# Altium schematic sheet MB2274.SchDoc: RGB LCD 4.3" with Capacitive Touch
size A3; Date: 25-FEB-2015; Author: A.B; CompanyName: STMicroelectronics; Address1: 12, Rue Jules HOROWITZ; Address2: 38019 Grenoble; Address3: FRANCE; DocumentNumber: 2; Revision: A.1; SheetNumber: 2; SheetTotal: 2; Project: STM32L4Rx-EVAL Daughter board
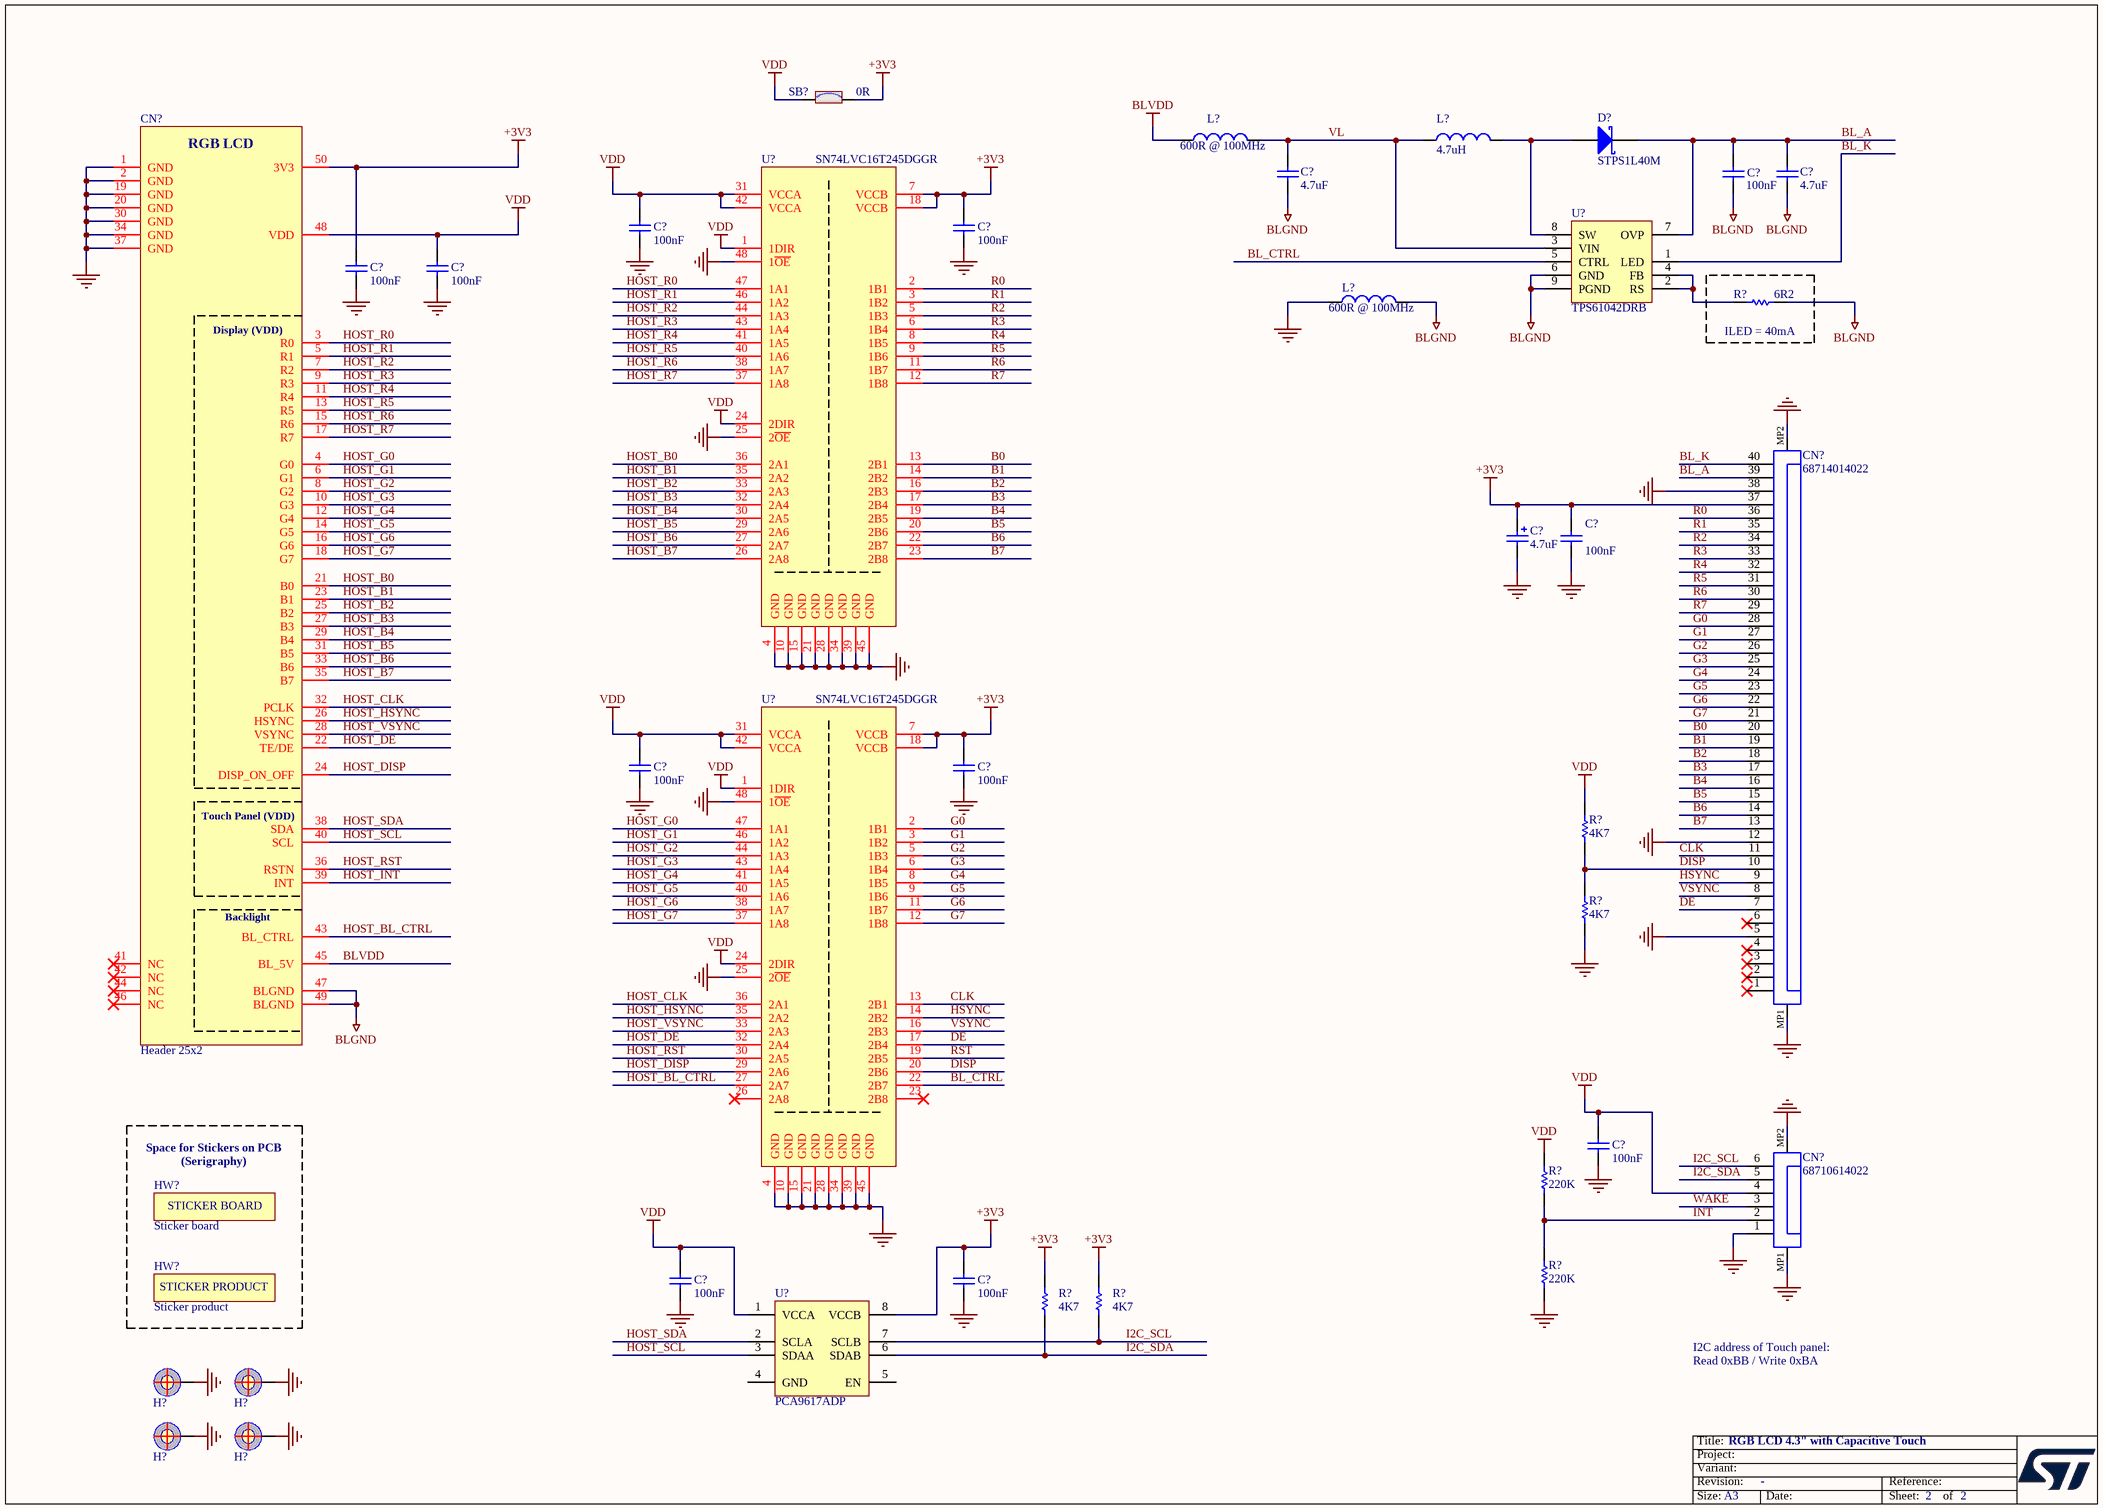
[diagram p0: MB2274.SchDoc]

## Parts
(Parts that share a designator on the sheet are numbered #1, #2 ... from top to bottom, then left to right.)
C?#1  value 4.7uF  [C1206_H1P25]  (hidden comment: Capacitor)
C?#2  value 100nF  [C0603]  (hidden comment: Capacitor)
C?#3  value 4.7uF  [C1206_H1P25]  (hidden comment: Capacitor)
C?#4  100nF  [0603C]
C?#5  100nF  [0603C]
C?#6  100nF  [0603C]
C?#7  100nF  [0603C]
C?#8  value 4.7uF  [CPOL_TAJ-A_1206_H180]  (hidden comment: Cap_POL_TANA)
C?#9  value 100nF  [C0603]  (hidden comment: Capacitor)
C?#10  100nF  [0603C]
C?#11  100nF  [0603C]
C?#12  value 100nF  [C0603]  (hidden comment: Capacitor)
C?#13  100nF  [0603C]
C?#14  100nF  [0603C]
CN?#1  value Header 25x2  [CON_SAMTEC_FTSH-125-01-F-DV-K]  (hidden comment: Header 25x2 LCD MODULE)
CN?#2  68714014022  [CON_WE_68714014022]
CN?#3  68710614022  [CON_WE_68710614022]
D?  STPS1L40M  [DIO_DO216-AA]
H?#1  POSITION HOLE  [HOLE_C9D4R5]  (value not drawn)  (no BOM)
H?#2  POSITION HOLE  [HOLE_C9D4R5]  (value not drawn)  (no BOM)
H?#3  POSITION HOLE  [HOLE_C9D4R5]  (value not drawn)  (no BOM)
H?#4  POSITION HOLE  [HOLE_C9D4R5]  (value not drawn)  (no BOM)
HW?#1  value Sticker board  [STICKER_BOARD_25X9]  (hidden comment: STICKER_BOARD)  (no BOM)
HW?#2  value Sticker product  [STICKER_PRODUCT_25X5]  (hidden comment: STICKER_PRODUCT)  (no BOM)
L?#1  value 600R @ 100MHz  [L0603]  (hidden comment: BEAD)
L?#2  value 4.7uH  [L1210_LQH]  (hidden comment: Inductor)
L?#3  value 600R @ 100MHz  [L0603]  (hidden comment: BEAD)
R?#1  value 6R2  [R0805_H0P5]  (hidden comment: Resistor)
R?#2  value 4K7  [R0603]  (hidden comment: Resistor)
R?#3  value 4K7  [R0603]  (hidden comment: Resistor)
R?#4  value 220K  [R0603]  (hidden comment: Resistor)
R?#5  value 220K  [R0603]  (hidden comment: Resistor)
R?#6  4K7  [0603R]
R?#7  4K7  [0603R]
SB?  value 0R  [SOLDER-BRIDGE_R0402-0R]  (hidden comment: SB_ON)
U?#1  SN74LVC16T245DGGR  [ICC_TSSOP48_12P5X6P1_P050]
U?#2  TPS61042DRB  [ICC_QFN8-EPAD_3X3_P065]
U?#3  SN74LVC16T245DGGR  [ICC_TSSOP48_12P5X6P1_P050]
U?#4  value PCA9617ADP  (hidden comment: PCA9617A)

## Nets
+3V3: C?#5.2 C?#6.2 C?#8.1 C?#9.2 C?#11.2 C?#14.2 CN?#1.50(3V3) CN?#2.37 R?#6.2 R?#7.2 SB?.2 U?#1.7(VCCB) U?#1.18(VCCB) U?#3.7(VCCB) U?#3.18(VCCB) U?#4.8(VCCB)
BLGND: C?#1.1 C?#2.1 C?#3.1 CN?#1.47(BLGND) CN?#1.49(BLGND) L?#3.2 R?#1.1 U?#2.6(GND) U?#2.9(PGND)
BLVDD: CN?#1.45(BL_5V) L?#1.1
GND: C?#4.1 C?#5.1 C?#6.1 C?#7.1 C?#8.2 C?#9.1 C?#10.1 C?#11.1 C?#12.1 C?#13.1 C?#14.1 CN?#1.1(GND) CN?#1.2(GND) CN?#1.19(GND) CN?#1.20(GND) CN?#1.30(GND) CN?#1.34(GND) CN?#1.37(GND) CN?#2.5 CN?#2.12 CN?#2.38 CN?#2.MP1 CN?#2.MP2 CN?#3.1 CN?#3.MP1 CN?#3.MP2 H?#1.1 H?#2.1 H?#3.1 H?#4.1 L?#3.1 R?#3.1 R?#5.1 U?#1.4(GND) U?#1.10(GND) U?#1.15(GND) U?#1.21(GND) U?#1.25(2~{OE}) U?#1.28(GND) U?#1.34(GND) U?#1.39(GND) U?#1.45(GND) U?#1.48(1~{OE}) U?#3.4(GND) U?#3.10(GND) U?#3.15(GND) U?#3.21(GND) U?#3.25(2~{OE}) U?#3.28(GND) U?#3.34(GND) U?#3.39(GND) U?#3.45(GND) U?#3.48(1~{OE})
VDD: C?#4.2 C?#7.2 C?#10.2 C?#12.2 C?#13.2 CN?#1.48(VDD) CN?#3.4 R?#2.2 R?#4.2 SB?.1 U?#1.1(1DIR) U?#1.24(2DIR) U?#1.31(VCCA) U?#1.42(VCCA) U?#3.1(1DIR) U?#3.24(2DIR) U?#3.31(VCCA) U?#3.42(VCCA) U?#4.1(VCCA)
B0: CN?#2.20 U?#1.13(2B1)
B1: CN?#2.19 U?#1.14(2B2)
B2: CN?#2.18 U?#1.16(2B3)
B3: CN?#2.17 U?#1.17(2B4)
B4: CN?#2.16 U?#1.19(2B5)
B5: CN?#2.15 U?#1.20(2B6)
B6: CN?#2.14 U?#1.22(2B7)
B7: CN?#2.13 U?#1.23(2B8)
BL_A: C?#2.2 C?#3.2 CN?#2.39 D?.2(K) U?#2.7(OVP)
BL_CTRL: U?#2.5(CTRL) U?#3.22(2B7)
BL_K: CN?#2.40 U?#2.1(LED)
CLK: CN?#2.11 U?#3.13(2B1)
DE: CN?#2.7 U?#3.17(2B4)
DISP: CN?#2.10 R?#2.1 R?#3.2 U?#3.20(2B6)
G0: CN?#2.28 U?#3.2(1B1)
G1: CN?#2.27 U?#3.3(1B2)
G2: CN?#2.26 U?#3.5(1B3)
G3: CN?#2.25 U?#3.6(1B4)
G4: CN?#2.24 U?#3.8(1B5)
G5: CN?#2.23 U?#3.9(1B6)
G6: CN?#2.22 U?#3.11(1B7)
G7: CN?#2.21 U?#3.12(1B8)
HOST_B0: CN?#1.21(B0) U?#1.36(2A1)
HOST_B1: CN?#1.23(B1) U?#1.35(2A2)
HOST_B2: CN?#1.25(B2) U?#1.33(2A3)
HOST_B3: CN?#1.27(B3) U?#1.32(2A4)
HOST_B4: CN?#1.29(B4) U?#1.30(2A5)
HOST_B5: CN?#1.31(B5) U?#1.29(2A6)
HOST_B6: CN?#1.33(B6) U?#1.27(2A7)
HOST_B7: CN?#1.35(B7) U?#1.26(2A8)
HOST_BL_CTRL: CN?#1.43(BL_CTRL) U?#3.27(2A7)
HOST_CLK: CN?#1.32(PCLK) U?#3.36(2A1)
HOST_DE: CN?#1.22(TE/DE) U?#3.32(2A4)
HOST_DISP: CN?#1.24(DISP_ON_OFF) U?#3.29(2A6)
HOST_G0: CN?#1.4(G0) U?#3.47(1A1)
HOST_G1: CN?#1.6(G1) U?#3.46(1A2)
HOST_G2: CN?#1.8(G2) U?#3.44(1A3)
HOST_G3: CN?#1.10(G3) U?#3.43(1A4)
HOST_G4: CN?#1.12(G4) U?#3.41(1A5)
HOST_G5: CN?#1.14(G5) U?#3.40(1A6)
HOST_G6: CN?#1.16(G6) U?#3.38(1A7)
HOST_G7: CN?#1.18(G7) U?#3.37(1A8)
HOST_HSYNC: CN?#1.26(HSYNC) U?#3.35(2A2)
HOST_INT: CN?#1.39(INT)
HOST_R0: CN?#1.3(R0) U?#1.47(1A1)
HOST_R1: CN?#1.5(R1) U?#1.46(1A2)
HOST_R2: CN?#1.7(R2) U?#1.44(1A3)
HOST_R3: CN?#1.9(R3) U?#1.43(1A4)
HOST_R4: CN?#1.11(R4) U?#1.41(1A5)
HOST_R5: CN?#1.13(R5) U?#1.40(1A6)
HOST_R6: CN?#1.15(R6) U?#1.38(1A7)
HOST_R7: CN?#1.17(R7) U?#1.37(1A8)
HOST_RST: CN?#1.36(RSTN) U?#3.30(2A5)
HOST_SCL: CN?#1.40(SCL) U?#4.3(SDAA)
HOST_SDA: CN?#1.38(SDA) U?#4.2(SCLA)
HOST_VSYNC: CN?#1.28(VSYNC) U?#3.33(2A3)
HSYNC: CN?#2.9 U?#3.14(2B2)
I2C_SCL: CN?#3.6 R?#7.1 U?#4.7(SCLB)
I2C_SDA: CN?#3.5 R?#6.1 U?#4.6(SDAB)
INT: CN?#3.2 R?#4.1 R?#5.2
R0: CN?#2.36 U?#1.2(1B1)
R1: CN?#2.35 U?#1.3(1B2)
R2: CN?#2.34 U?#1.5(1B3)
R3: CN?#2.33 U?#1.6(1B4)
R4: CN?#2.32 U?#1.8(1B5)
R5: CN?#2.31 U?#1.9(1B6)
R6: CN?#2.30 U?#1.11(1B7)
R7: CN?#2.29 U?#1.12(1B8)
RST: U?#3.19(2B5)
VL: C?#1.2 L?#1.2 L?#2.1 U?#2.3(VIN)
VSYNC: CN?#2.8 U?#3.16(2B3)
WAKE: CN?#3.3
NetD?_1: D?.1(A) L?#2.2 U?#2.8(SW)
NetR?#1_2: R?#1.2 U?#2.2(RS) U?#2.4(FB)

Not connected (* = marked no-connect by the designer): CN?#1 41(NC)* 42(NC)* 44(NC)* 46(NC)*; CN?#2 1* 2* 3* 4* 6*; U?#3 23(2B8)* 26(2A8)*; U?#4 4(GND) 5(EN)

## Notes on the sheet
- (near R?#1) ILED = 40mA
- (near HW?#1) Space for Stickers on PCB (Serigraphy)
- I2C address of Touch panel:
- Read 0xBB / Write 0xBA

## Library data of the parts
C?#1 C?#3 = MCD-00013: Capacitor, MLCC, 4.7uF, 50V, X7R, +/-10%, 1206, T=1.27mm; Part_Preference: Recommended; Manufacturer: AVX; Manufacturer_Part_Number: 12065C475KAT2A; Order_Code_RS: 178-0947; Component_Country_Of_Origin: China, Penang; ShowFields: YES; ID: 2466
C?#2 = MCD-01099: Capacitor, MLCC, 100nF, 50V, X7R, +/-10%, 0603, T=0.8mm; BMS_Part_Number: 9142278; Part_Preference: Recommended; Manufacturer: YAGEO; Manufacturer_Part_Number: CC0603KRX7R9BB104; Order_Code_RS: 669-8767; Component_Country_Of_Origin: China; ShowFields: YES; ID: 3397
C?#4-C?#7 C?#10 C?#11 C?#13 C?#14 = CAP: Capacitor; Value: 100pF; Ordered by: Subcon; ECCN_US/EU: NA
C?#8 = MCD-00007: Capacitor, Tantalum, 4.7uF, 16V, 4R, +/-10%, Type_A (3216 metric), T=1.6mm; Part_Preference: Recommended; Manufacturer: AVX; Manufacturer_Part_Number: TAJA475K016R; Order_Code_RS: 464-9132; Component_Country_Of_Origin: El Salvador; ShowFields: YES; ID: 2473
C?#9 C?#12 = MCD-00211: Capacitor, MLCC, 100nF, 16V, X7R, +/-10%, 0603, T=0.8mm; Part_Preference: Recommended; Manufacturer: YAGEO; Manufacturer_Part_Number: CC0603KRX7R7BB104; Order_Code_RS: 669-8763; Component_Country_Of_Origin: China; ShowFields: YES; ID: 2659
CN?#1 = Header 25x2 LCD MODULE: Header, 25x2, 1.27mm, VR, SMD, T=5.97mm; Internal_Part_Number: MCD-01187; Part_Type: Connector; Part_Preference: Recommended; Manufacturer: SAMTEC; Manufacturer_Part_Number: FTSH-125-01-F-DV-K; Partial_Alternate_Internal_Part_Number: MCD-03150; Order_Code_RS: 208-1518; Component_Country_Of_Origin: China, Costa Rica, Malaysia, USA, Vietnam; ShowFields: YES; ID: 3304
CN?#2 = MCD-02724: Socket_FFC/FPC, 40pins, 0.5mm, RA, SMD, T=2.1mm, TOP Contact; Part_Type: Connector; Part_Preference: Recommended; Manufacturer: WURTH ELEKTRONIK; Value: Socket_FFC/FPC_68714014022; Order_Code_RS: 763-6732; ShowFields: YES; ID: 4821
CN?#3 = MCD-02725: Socket_FFC/FPC, 6pins, 0.5mm, RA, SMD, T=2.1mm, TOP Contact; Part_Type: Connector; Part_Preference: Recommended; Manufacturer: WURTH ELEKTRONIK; Value: Socket_FFC/FPC_68710614022; Order_Code_RS: 763-2648; ShowFields: YES; ID: 4837
D? = MCD-00033: Low Drop power Schottky rectifier(1A, 40V, 0.4V); BMS_Part_Number: 9151085; Part_Type: Diode; Part_Preference: Recommended; Manufacturer: STMICROELECTRONICS; Manufacturer_HQ_COO: EU; Component_Country_Of_Origin: China; ShowFields: YES; ID: 2485
H?#1-H?#4 = POSITION HOLE: Fitted: NO
HW?#1 = MCD-00235: Sticker Board 25x9 mm; Part_Preference: Recommended; Part_Type: Misc; ID: 2632; ShowFields: YES
HW?#2 = MCD-02189: Sticker product 25x5 mm; Part_Preference: Recommended; Part_Type: Misc; ID: 4289; ShowFields: YES
L?#1 L?#3 = MCD-00047: Ferrite bead, 600R @1 00MHz, +/-25%, 350mA, 0R5, 0603, T=0.8mm; Part_Type: Inductor; Part_Preference: Recommended; Manufacturer: TAI-TECH; Manufacturer_Part_Number: FCM1608KF-601T03; Component_Country_Of_Origin: Unknown; ShowFields: YES; ID: 2546
L?#2 = MCD-00048: Inductor, 4.7uH, +/-30%, 1A, 180mR, 1210, T=1.7mm; Part_Preference: Recommended; Manufacturer: MURATA; Manufacturer_Part_Number: LQH32PN4R7NN0L; Order_Code_RS: 167-4086; Component_Country_Of_Origin: Japan; ShowFields: YES; ID: 2544
R?#1 = MCD-02728: Resistor, 6R2, 0805, +/-1%, 1/8W; Part_Preference: Recommended; Manufacturer: YAGEO; Manufacturer_Part_Number: RC0805FR-076R2L; ShowFields: YES; ID: 4840
R?#2 R?#3 = MCD-00219: Resistor, 4K7, 0603, +/-1%, 1/10W; Part_Preference: Recommended; Manufacturer: YAGEO; Manufacturer_Part_Number: RC0603FR-074K7L; Component_Country_Of_Origin: China; ShowFields: YES; ID: 2648
R?#4 R?#5 = MCD-00347: Resistor, 220K, 0603, +/-1%, 1/10W; Part_Preference: Recommended; Manufacturer: YAGEO; Manufacturer_Part_Number: RC0603FR-07220KL; Component_Country_Of_Origin: China; ShowFields: YES; ID: 2930
R?#6 R?#7 = Res_1K_1%_0603: Resistor,4.7K,0603,1%,YAGEO; Manuf_Part_1: RC0603FR-074K7L; Ordered by: Subcon; Fitted: YES
SB? = MCD-01618: Resistor, 0R, SB0402, 5%, 0.063W; Manufacturer_Part_Number: RC0402JR-070RL; Manufacturer: YAGEO; Part_Preference: Recommended; Order_Code_RS: 618-5804; Component_Country_Of_Origin: China; ID: 3718; ShowFields: YES
U?#1 U?#3 = SN74LVC16T245DGGR: Bus Transceiver, 16-bit Dual-Supply bus transceiver with configurable Level-Shifting/Voltage translation and Tri-State outputs; Internal_Part_Number: MCD-01074; Part_Type: IC; Part_Preference: Recommended; Manufacturer: TEXAS INSTRUMENTS; Order_Code_RS: 922-2381; Component_Country_Of_Origin: Malaysia; ShowFields: YES; ID: 3418
U?#2 = MCD-02727: 30-V, 500-mA switch boost converter in QFN-8 for white LED applications; Part_Type: IC; Part_Preference: Recommended; Manufacturer: TEXAS INSTRUMENTS; ShowFields: YES; ID: 4839
U?#4 = MCD-03055: Level-Translating FM+ I2C Bus Repeater; Part_Type: IC; Part_Preference: Recommended; Manufacturer: NXP; Manufacturer_Part_Number: PCA9617ADPJ; Full_Alternate_Internal_Part_Number: MCD-01949; Order_Code_RS: 124-2347; Component_Country_Of_Origin: Malaysia°; ShowFields: YES; ID: 5171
